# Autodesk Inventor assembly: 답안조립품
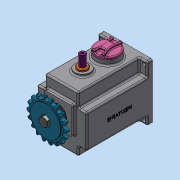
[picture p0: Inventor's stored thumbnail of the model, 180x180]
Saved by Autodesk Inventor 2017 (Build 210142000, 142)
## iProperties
Part Number: 답안조립품
Material: 일반
Document SubType Name: Assembly
Designer: MRC
Author: MRC
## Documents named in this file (16)
- C:\Users\MRC\Desktop\720212V1008\답안조립품.iam
- C:\Users\MRC\Desktop\720212V1008\본체.ipt
- C:\Users\MRC\Desktop\720212V1008\멈춤나사 M3.ipt
- C:\Users\MRC\Desktop\720212V1008\메인 축.ipt
- C:\Users\MRC\Desktop\720212V1008\베어링 608.ipt
- C:\Users\MRC\Desktop\720212V1008\베어링 6003.ipt
- C:\Users\MRC\Desktop\720212V1008\볼트 M4 x 10.ipt
- C:\Users\MRC\Desktop\720212V1008\부시.ipt
- C:\Users\MRC\Desktop\720212V1008\상부 캡.ipt
- C:\Users\MRC\Desktop\720212V1008\서브 축.ipt
- C:\Users\MRC\Desktop\720212V1008\스프로킷.ipt
- C:\Users\MRC\Desktop\720212V1008\슬라이더.ipt
- C:\Users\MRC\Desktop\720212V1008\오일 실 8 x 22 x 7.ipt
- C:\Users\MRC\Desktop\720212V1008\오일 실 17 x 32 x 8.ipt
- C:\Users\MRC\Desktop\720212V1008\커버.ipt
- C:\Users\MRC\Desktop\720212V1008\키 5 x 5.ipt
